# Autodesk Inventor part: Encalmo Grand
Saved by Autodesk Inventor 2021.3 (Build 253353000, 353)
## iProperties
Created: 2022-06
Part Number: Encalmo Grand
Material: Generic
Document SubType Name: Modeling
Designer: Administrator
Density: 1 g/cm^3
Appearance: Default
Title: Encalmo Grand v9
Author: Administrator
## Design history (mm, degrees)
feature "Encalmo Grand" [Body]
feature "Encalmo Grand (1)" [Body]
feature "Socket Body" [Body]
feature "Shade Ring" [Body]
feature "Shade Ring +Collar" [Body]
feature "Socket" [Body]
feature "Body1"
feature "Metal Strain Relief" [Body]
feature "Fabric Cord (1)" [Body]
feature "Stem (Threaded)" [Body]
feature "Cap (Threaded)" [Body]
feature "5M Set Screw" [Body]
feature "T9-Bulb" [Body]
body "Solid1"
body "Solid2"
body "Solid3"
body "Solid4"
body "Solid5"
body "Solid6"
body "Solid7"
body "Solid8"
body "Solid9"
body "Solid10"
body "Solid11"
body "Solid12"
body "Solid13"
